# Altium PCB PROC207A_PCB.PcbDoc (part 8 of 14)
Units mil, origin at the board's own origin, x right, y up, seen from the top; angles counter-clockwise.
Board outline 4094.49 x 3724.79 mil, 8 copper layers (Top Layer, L2_GND1, L3_SIG1, L4_PWR1, L5_PWR2, L6_SIG2, L7_GND2, Bottom Layer), stack 58.1 mil thick; 584 components, 399 nets, 8440 pads, 5258 vias.
Unrouted connection lines stored in the file: 9.
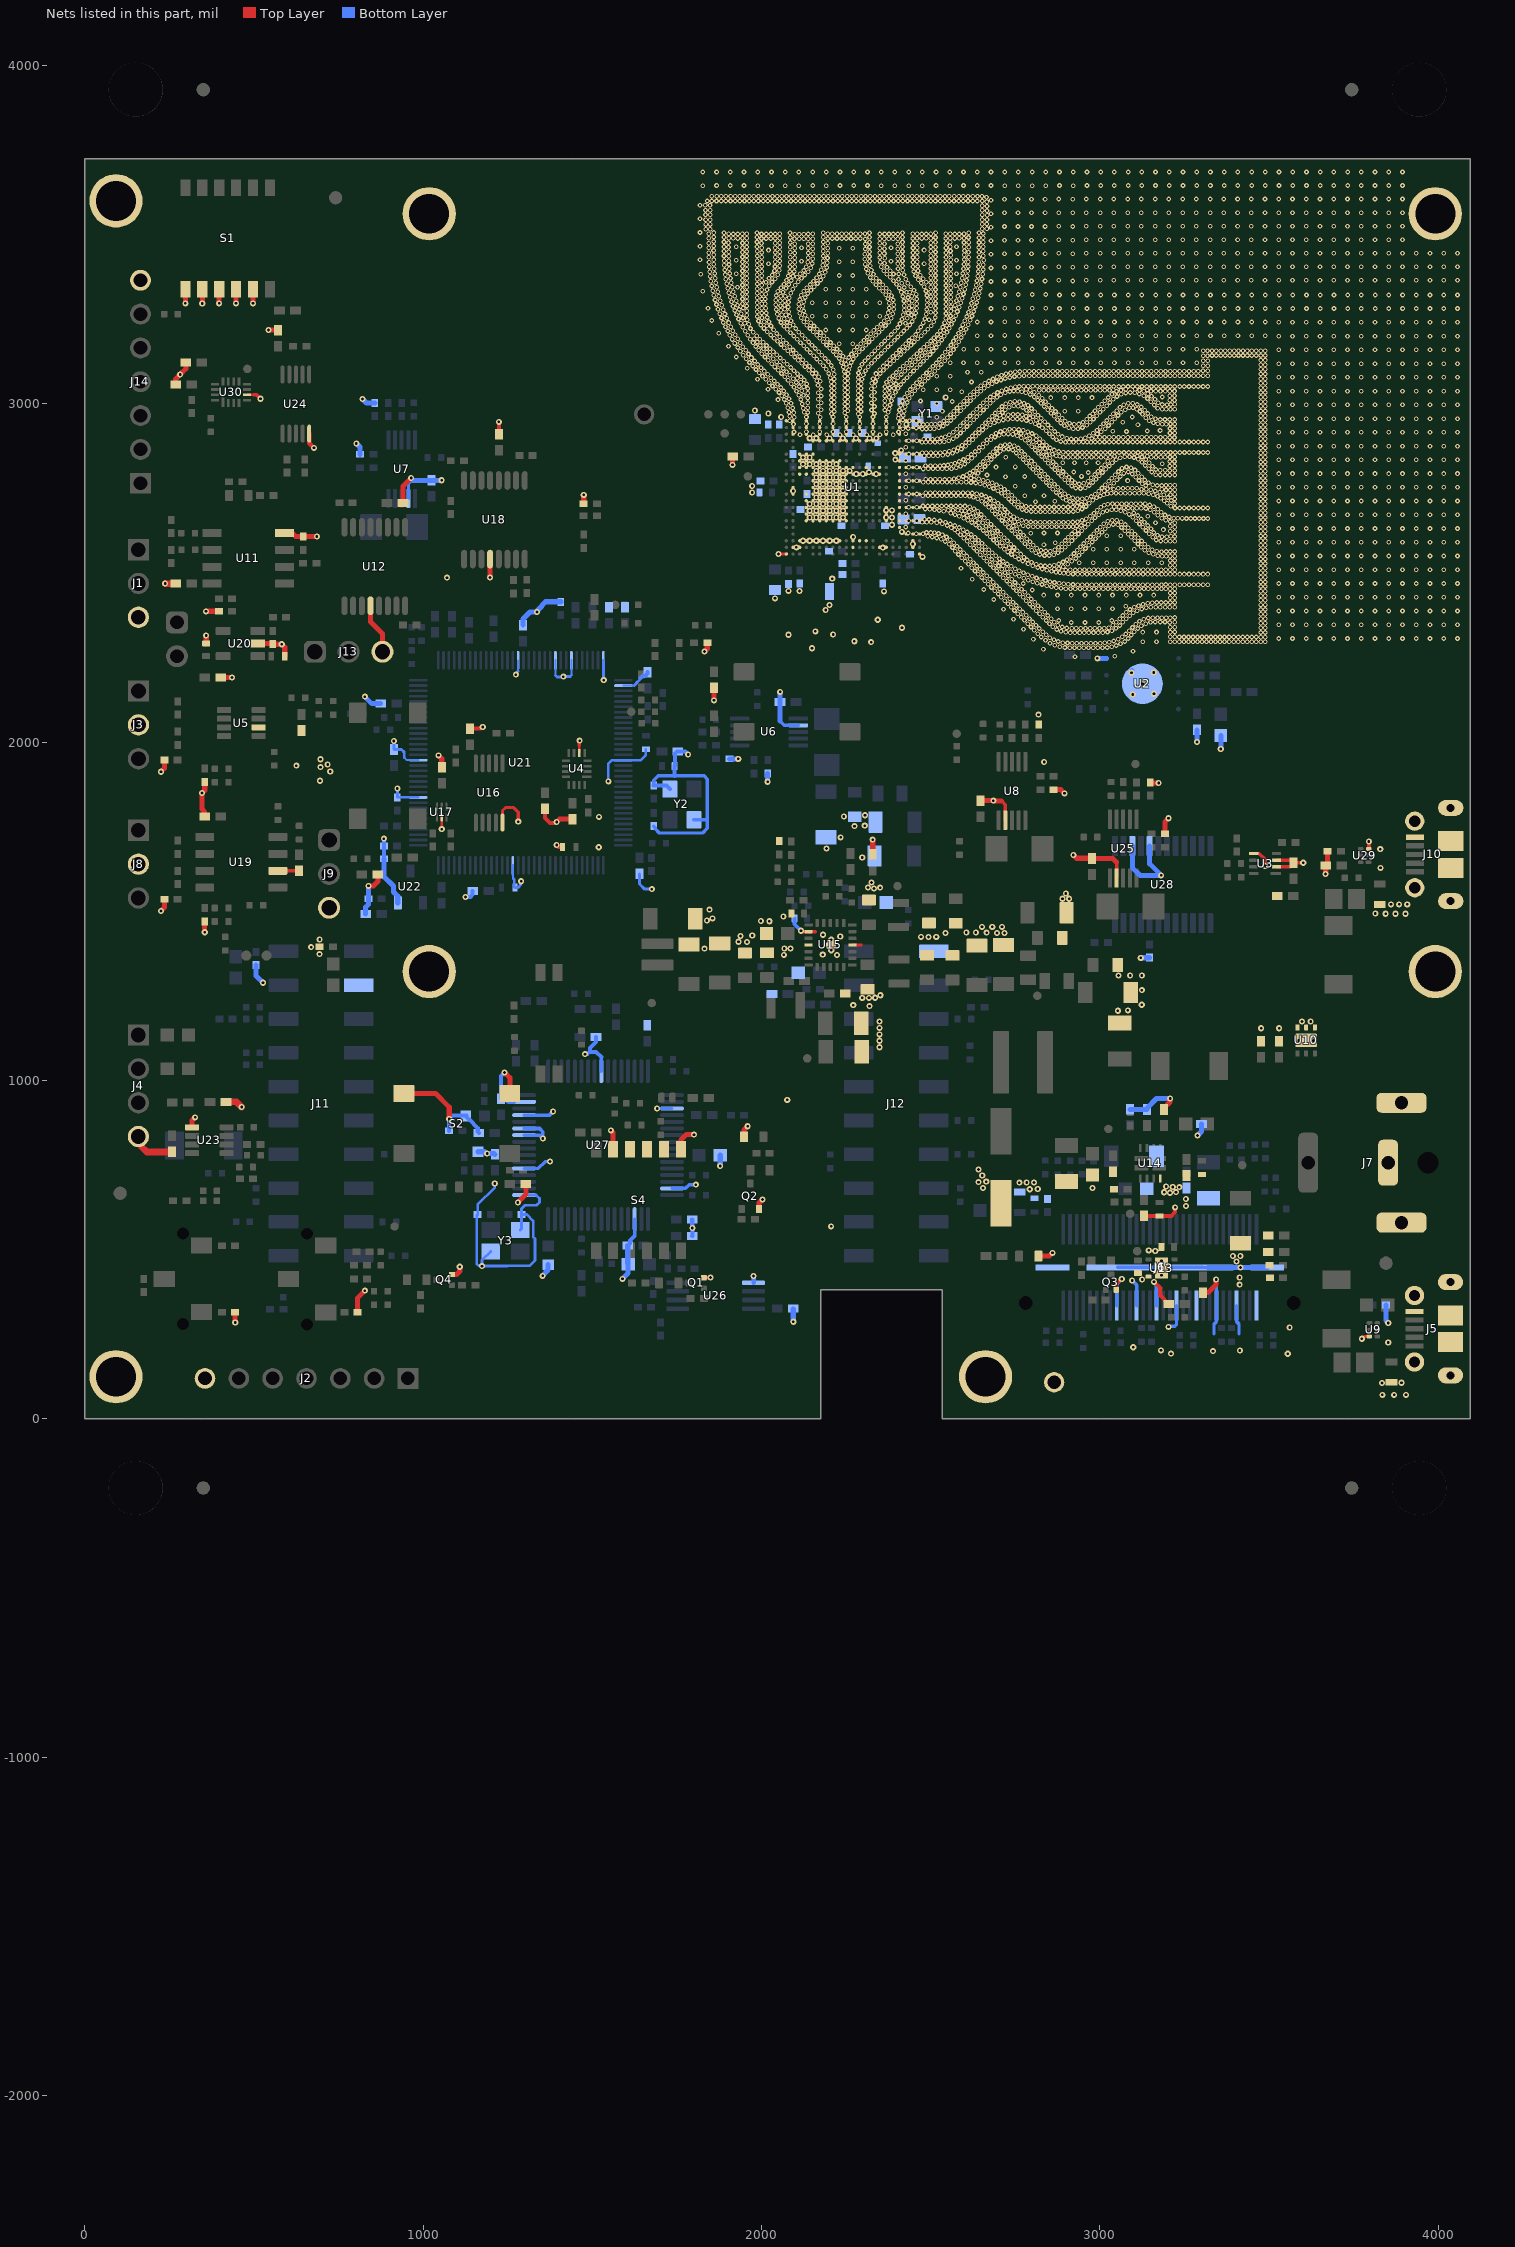
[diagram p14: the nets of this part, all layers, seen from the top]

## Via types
v1: diameter 13.77, hole 7, Top Layer to L2_GND1, tented top, 4306 vias
v2: diameter 18, hole 8, Top Layer to Bottom Layer, tented both sides, 946 vias
v3: diameter 19.68, hole 8, Top Layer to Bottom Layer, tented both sides, 6 vias

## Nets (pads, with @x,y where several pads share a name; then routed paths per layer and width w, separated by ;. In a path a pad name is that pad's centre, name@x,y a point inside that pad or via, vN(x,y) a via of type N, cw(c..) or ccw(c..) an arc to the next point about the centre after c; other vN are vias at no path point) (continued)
GND: C1.1 C2.1 C3.1 C4.1 C5.1 C6.2 C7.1 C8.1 C9.1 C10.1 C11.1 C12.1 C13.2 C14.1 C15.2 C16.1 C17.1 C18.1 C19.1 C20.1 C21.1 C22.1 C24.1 C25.1 C26.1 C27.1 C30.2 C31.2 C32.1 C33.1 C34.2 C35.1 C36.2 C37.1 C38.1 C39.1 C40.2 C41.2 C42.1 C43.2 C44.2 C45.1 C46.1 C47.2 C48.2 C49.2 C50.2 C51.2 C52.1 C53.2 C54.2 C55.2 C56.2 C57.2 C58.2 C59.2 C60.2 C61.2 C62.2 C63.2 C64.2 C65.2 C66.2 C67.1 C68.2 C70.2 C71.2 C72.1 C73.2 C74.2 C75.1 C76.2 C77.1 C78.1 C79.2 C80.2 C81.2 C82.1 C83.2 C84.2 C85.1 C86.1 C87.2 C88.1 C89.2 C90.2 C91.1 C92.2 C93.2 C94.2 C95.1 C96.1 C97.1 C98.1 C99.1 C100.2 C102.1 C103.1 C104.2 C105.2 C106.1 C107.2 C108.2 C109.1 C110.1 C111.1 C112.1 C113.1 C114.2 C115.2 C116.1 C117.1 C118.1 C119.2 C120.2 C121.1 C123.2 C124.2 C125.1 C126.1 C127.2 C128.2 C130.2 C131.1 C132.2 C133.2 C134.1 C135.2 C136.2 C137.2 C138.2 C139.2 C140.2 C141.2 C142.1 C143.2 C144.2 C145.2 C146.1 C147.2 C148.2 C149.1 C150.2 C151.1 C152.2 C153.2 C154.1 C155.1 C156.1 C157.1 C158.2 D6.1 D10.1 J1.3 J2.7 J3.2 J4.4 J5.5 J5.6 J5.7 J5.8 J5.9 J5.10 J5.11 J6.18 J6.24 J6.30 J6.36 J6.42 J6.48 J6.54 J6.60 J6.MP1 J6.MP2 J6.MP3 J6.MP4 J7.2 J7.S1 J7.S2 J8.2 J9.3 J10.5 J10.6 J10.7 J10.8 J10.9 J10.10 J10.11 J11.4 J12.2 J13.3 J14.7 pad.TH1 pad.TH2 pad.TH9 pad.TH10 Q1.2 Q2.2 Q3.2 Q4.2 R6.1 R10.2 R11.1 R20.1 R23.1 R33.1 R57.1 R71.1 R72.1 R73.2 R74.1 R75.1 R84.1 R86.1 R92.1 R101.1 R103.1 R113.1 R114.1 R116.1 R117.1 R144.1 R148.1 R150.1 R158.1 R162.1 R191.2 R194.2 R205.1 R208.1 R215.2 R218.1 R234.1 R239.1 R260.1 R265.2 R272.1 R276.2 R289.1 S1.7 S1.8 S1.9 S1.10 S1.11 S2.1 S2.2 S4.7 S4.8 S4.9 S4.10 S4.11 TP21.1 U1.A1 U1.A2 U1.A4 U1.A6 U1.A8 U1.A10 U1.A12 U1.A14 U1.A16 U1.A18 U1.A21 U1.AA1 U1.AA21 U1.B1 U1.B2 U1.B4 U1.B6 U1.B8 U1.B10 U1.B12 U1.B14 U1.B16 U1.B18 U1.B19 U1.B20 U1.C1 U1.C2 U1.C3 U1.C4 U1.C5 U1.C6 U1.C7 U1.C8 U1.C9 U1.C10 U1.C11 U1.C12 U1.C13 U1.C14 U1.C15 U1.C16 U1.C17 U1.C18 U1.D1 U1.D2 U1.D3 U1.D6 U1.D7 U1.D8 U1.D9 U1.D10 U1.D11 U1.D12 U1.D13 U1.D14 U1.D15 U1.D16 U1.D17 U1.E3 U1.F1 U1.F2 U1.F3 U1.F14 U1.F15 U1.F16 U1.F20 U1.G3 U1.G8 U1.G9 U1.G20 U1.H1 U1.H2 U1.H3 U1.H4 U1.H9 U1.J3 U1.J4 U1.J8 U1.J9 U1.J19 U1.K1 U1.K2 U1.K3 U1.K4 U1.K9 U1.K19 U1.L3 U1.L4 U1.L8 U1.L9 U1.L19 U1.L20 U1.M1 U1.M2 U1.M3 U1.M4 U1.M8 U1.M9 U1.M10 U1.M11 U1.M12 U1.M13 U1.M14 U1.M15 U1.M16 U1.N3 U1.N4 U1.N7 U1.N8 U1.N9 U1.N10 U1.N11 U1.N12 U1.N13 U1.N14 U1.N15 U1.N16 U1.N19 U1.P1 U1.P2 U1.P3 U1.P4 U1.P7 U1.P8 U1.P9 U1.P10 U1.P11 U1.P12 U1.P13 U1.P14 U1.P15 U1.P16 U1.P19 U1.R3 U1.R4 U1.R7 U1.R8 U1.R9 U1.R10 U1.R11 U1.R12 U1.R13 U1.R14 U1.R15 U1.R16 U1.R19 U1.T1 U1.T2 U1.T3 U1.T4 U1.T7 U1.T8 U1.T9 U1.T10 U1.T11 U1.T12 U1.T13 U1.T14 U1.T15 U1.T16 U1.T19 U1.U3 U1.U4 U1.U6 U1.U7 U1.U8 U1.U9 U1.U10 U1.U11 U1.U12 U1.U13 U1.U14 U1.U15 U1.U16 U1.U19 U1.V1 U1.V2 U1.V3 U1.V6 U1.V7 U1.V8 U1.V9 U1.V12 U1.V13 U1.V14 U1.V15 U1.V16 U1.V19 U1.W3 U1.W6 U1.W7 U1.W8 U1.W9 U1.W19 U1.W20 U1.Y1 U1.Y2 U1.Y3 U1.Y11 U1.Y12 U1.Y20 U2.4 U2.9 U3.2 U3.3 U3.5 U4.6 U5.2 U6.7 U7.7 U8.7 U9.3 U10.1 U10.2 U10.3 U10.7@3610.07,1118.68 U11.4 U12.4 U13.3 U13.7@3182.65,445.74 U14.12 U15. U15.2 U15.4 U15.16 U16.5 U17.2 U18.4 U19.2 U20.2 U21.10 U21.17 U21.48 U21.55 U21.58 U21.64 U21.66 U21.80 U21.114 U22.2 U23.5 U24.5 U25.7 U26.5 U27.1 U27.5 U27.10 U27.11 U27.13 U27.15 U27.25 U27.35 U27.47 U27.51 U28.3 U28.5 U29.3 U30.6 Y1.2 Y1.4 Y2.2 Y2.4 Y3.2 Y3.4 | length 10594.6
  Top Layer w6.5: v2(1054.79,1743.16) U17.2@1054.8,1778.05
  Top Layer w7: U30.6@479.11,3026.97 498.53,3026.97 ; U4.6@1461.61,1968.51 1461.61,1991.8
  Top Layer w9: U16.5@1234.33,1762.65 1234.33,1798.01 1243.1,1806.78 1267.22,1806.78 1280.94,1793.06 v2(1280.94,1765.37)
  Top Layer w10: Q1.2@1829.27,417.33 1849.22,417.33 v2(1849.44,417.55) ; v2(2050.39,2556.74) 2050.56,2556.57 2073.3,2556.57 U1.AA21@2073.47,2556.4 ; U1.Y20@2093.15,2576.08 v2(2103,2576.08) U1.W20@2112.84,2576.08 ; U15.2@2138.7,1440.14 2159.3,1440.14 2159.35,1440.09 ; U15.16@2268.62,1400.77 2295.72,1400.77 ; U1.G20@2349.06,2576.08 U1.F20@2368.75,2576.08 ; U1.B20@2447.49,2576.08 v2(2447.49,2585.92) U1.B19@2447.49,2595.77 ; U1.A21@2467.17,2556.4 2467.43,2556.4 2475.67,2548.16 v2(2475.93,2548.16) ; 2709.76,1826.64 2720.79,1815.61 U8.7@2720.79,1769.27 ; C133.2@2976.64,1657.11 C133.2@2977.36,1656.39 ; Q3.2@3048.73,381.35 3048.73,397.24 v2(3064.99,413.5) ; U25.7@3049.64,1599.03 3049.64,1645.37 ; U3.5@3464.21,1671.03 3471.71,1671.03 3489,1653.74 v2(3489,1634) ; U3.2@3522.36,1631.66 3563.97,1631.66 3572.12,1639.81 C36.2@3572.12,1643.75 ; U3.3@3522.36,1651.35 3564.52,1651.35 C36.2@3572.12,1643.75 ; v2(3601.47,1643.75) C36.2@3572.12,1643.75 ; v2(3774.61,236.71) 3776.77,236.71 3783.6,243.53 U9.3@3796.72,243.53
  Top Layer w10.8: 498.53,3026.97 507.35,3026.97 v2(518.82,3015.49) ; U19.2@570.55,1620.14 632.82,1620.14 C110.1@632.96,1620 ; 1461.61,1991.8 1461.61,2004.04 v2(1462.35,2004.78) ; v2(2116.54,1442.8) 2117.92,1441.42 2123.04,1441.42 2124.33,1440.14 U15.2@2132.29,1440.14
  Top Layer w12: U24.5@663.06,2912.26 663.06,2883.9 v2@676.55,2870.41 ; C104.2@1138.39,2040.95 1169.79,2040.95 1174.26,2045.42 v2(1175.88,2045.42) ; C107.2@1223.43,2910.43 1223.43,2947.21 v2(1223.53,2947.31) ; R6.1@1360.12,1803.04 1360.12,1775.81 1374.18,1761.75 1390.61,1761.75 1392.95,1764.09 v2(1394.57,1764.09) ; v2(1394.47,1696.19) 1399.74,1690.92 C108.2@1411.68,1690.92 ; R33.1@3130.93,600.03 C68.2@3175.93,600.03 3211.37,600.03 3222.8,611.46 v2(3222.8,625.19) ; v2(3160.39,404.95) 3178.79,386.55 3178.79,364.8 R92.1@3203.79,339.8 ; U29.3@3795.04,1684.93 3795.14,1685.03 3795.14,1706.42 v2(3795.24,1706.52)
  Top Layer w15: v2@224.29,1501.17 234.64,1511.53 C111.1@234.64,1535.77 ; v2@224.45,1912.88 234.81,1923.24 C39.1@234.81,1947.48 ; C136.2@267.48,3058.04 267.48,3073.34 v2(281.32,3087.18) 298.33,3104.19 R272.1@298.33,3122.76 ; v2@296.89,3298.8 S1.7@296.89,3339.18 ; U23.5@316.77,861.92 316.77,882.42 v2(325.68,891.33) ; v2@345.5,3297.83 346.23,3297.83 347.04,3298.64 S1.8@347.04,3339.03 ; R144.1@354.01,1470.77 v2(354.07,1438.37) v2(354.07,1438.37) ; C109.1@354.01,1780.14 354.01,1794.45 345.82,1802.65 v2(345.82,1849.79) 354.18,1858.16 R71.1@354.18,1882.48 ; v2(357.7,2386.96) 357.98,2387.24 R158.1@395.99,2387.24 ; v2@396.89,3298.8 S1.9@396.89,3339.18 ; C38.1@401.43,2191.85 434.53,2191.85 v2(434.67,2191.71) ; R205.1@443.81,315.23 444.01,315.02 444.01,284.74 v2(444.22,284.54) ; v2@446.89,3298.8 S1.10@446.89,3339.18 ; v2@496.89,3298.8 S1.11@496.89,3339.18 ; U20.2@510.67,2291.81 553.7,2291.81 R86.1@555.67,2289.84 v2(581.89,2289.84) 590.67,2281.05 C51.2@590.67,2254.41 ; v2(542.61,3218.78) 542.87,3218.52 570.41,3218.52 C135.2@570.67,3218.25 ; U11.4@590.18,2618.79 612.27,2618.79 622.9,2608.16 R162.1@645.19,2608.16 685.49,2608.16 v2(685.64,2608.3) ; R208.1@806.26,314.86 806.26,357.81 v2(827.31,378.87) ; v2(838.3,1575.48) 852.9,1575.48 865.89,1588.47 R215.2@865.89,1609.44 ; U12.4@844.1,2403.24 844.1,2356.36 879.43,2321.03 J13.3@879.43,2267.59 ; C41.2@940.24,2707.58 940.24,2757.15 v2(964.38,2781.29) ; S2.1@943.03,961.54 1036.63,961.54 1076.89,921.27 v2(1076.89,886.08) ; v2(1045.06,1961.26) 1054.8,1951.51 C52.1@1054.8,1925.79 ; Q4.2@1084.87,426.48 1098.61,426.48 1108.57,436.44 1107.86,437.15 v2(1107.86,449.58) ; v2(1197.46,2487.03) 1197.57,2487.14 1197.57,2541.45 U18.4@1197.68,2541.56 ; v2(1240.43,1023.85) 1256.02,1008.27 S2.2@1256.02,961.54 ; v2(1279.6,639.72) 1303.26,663.38 C53.2@1303.26,694.37 ; v2(1394.57,1764.09) 1403.26,1772.77 C40.2@1441.72,1772.77 ; C134.1@1474.49,2705 v2(1474.49,2731.49) ; v2(1554.55,852.9) 1561.51,845.93 S4.11@1561.51,796.87 ; S4.7@1761.51,796.87 1761.51,824.37 1778.08,840.94 1798.63,840.94 1798.8,840.77 1799.27,840.77 v2@1799.44,840.94 ; v2(1831.59,2268.33) 1831.59,2268.43 1839.67,2276.51 R276.2@1839.67,2294.33 ; v2(1859.79,2124) R265.2@1859.79,2160.77 ; v2(1914.48,2820.04) 1914.67,2820.23 1914.67,2844.11 C31.2@1915.05,2844.49 ; D10.1@1948.18,834.24 1948.29,834.35 1948.29,854.31 v2(1958.9,864.93) ; Q2.2@1992.56,620.43 1992.56,637.94 v2(2003.21,648.59) ; C59.2@2647.79,1827.36 2648.11,1827.68 2684.91,1827.68 2685.88,1826.72 2688,1826.72 2688.08,1826.64 2709.76,1826.64 ; D6.1@2818.58,481.14 2850.59,481.14 v2(2860.09,490.65) ; R116.1@2863.48,1859.92 2884.9,1859.92 v2(2895.9,1848.92) ; v2(2921.92,1666.58) 2931.39,1657.11 C133.2@2976.64,1657.11 ; C133.2@2977.36,1656.39 3038.61,1656.39 3049.64,1645.37 ; R150.1@3148.69,1881.62 3150.32,1880 v2@3173.68,1880 ; R74.1@3189.26,914.54 3189.26,918.48 3207.5,936.72 3207.5,946.31 v2(3208.07,946.89) ; R148.1@3192.33,1729.68 3192.33,1764.32 v2@3203.12,1775.11 ; R11.1@3305.55,372.91 3319.86,372.91 3343.99,397.04 v2(3343.99,411.59) ; v2(3667.11,1610.37) 3667.87,1611.13 3667.87,1634.49 3673.11,1639.72 R260.1@3673.11,1677.42 R260.1@3670.89,1679.64
  Top Layer w16: C112.1@358.31,2291.81 358.31,2315.18 v2(358.45,2315.32) ; R84.1@2328.26,1670.63 2328.5,1670.88 v2(2328.5,1712.23)
  Top Layer w20: J4.4@158.07,834.5 166.29,826.28 166.29,805.83 183.05,789.08 C132.2@256.77,789.08 ; v2(237.25,2469.04) 237.5,2468.79 C65.2@268.37,2468.79 ; C123.2@417.15,937.13 448.3,937.13 v2(463.4,922.04)
  Bottom Layer w6: 943.92,1955.22 951.89,1947.26 U21.17@985.36,1947.26 ; 1280.53,2210.56 U21.48@1280.53,2242.37 ; 1390.87,2197.77 U21.55@1390.87,2242.47 ; 1438.11,2198.9 U21.58@1438.11,2242.47 ; U21.66@1591.66,2167.67 1623.73,2167.67
  Bottom Layer w7: C115.2@923.91,1836.96 U21.10@985.36,1836.96 ; U21.114@1264.89,1636.17 1264.95,1612.25 1265.05,1612.14 1265.05,1608.47 1265.2,1608.33 1265.2,1598.11 1266.05,1597.26
  Bottom Layer w8: Y3.2@1199.96,495.1 1173.98,469.11 v2(1173.98,451.33) ; v2(1211.55,695.75) 1211.55,683.98 1160.84,633.28 C147.2@1160.84,604 1158.05,601.2 1158.05,458.47 1163.27,453.25 1172.06,453.25 v2(1173.98,451.33) ; Y3.4@1286.58,558.09 1290.73,562.24 C148.2@1290.73,604 ; U27.1@1298.34,661.42 1333.88,661.42 1343.6,651.7 1343.6,639.9 1335.16,631.46 1301.13,631.46 1290.73,621.05 C148.2@1290.73,604 ; v2(1547.1,1884.39) 1547.29,1884.58 1547.29,1936.92 1557.57,1947.19 U21.80@1591.66,1947.19 1643.19,1947.19 1658,1962 C114.2@1658,1979.25 ; J6.MP3@3302.69,447.65 3319.34,447.65 J6.MP3@3319.56,447.42 ; v2(1173.98,451.33) 1174.42,451.78 1248.33,451.78 1248.77,452.23 1314.64,452.23 1330.71,468.3 1330.71,532.51 1325.13,538.08 1325.13,585.17 1306.3,604 C148.2@1290.73,604
  Bottom Layer w8.7: v2(913.18,2003.61) 913.13,2003.55 C116.1@913.07,1978.49 C116.1@913.07,1978.49 936.06,1978.49 943.92,1970.63 943.92,1955.22 ; C115.2@923.42,1837.44 923.49,1837.51 923.49,1863.23 v2(923.55,1863.29) ; 1266.05,1597.26 1269.09,1594.22 1269.09,1572.03 C127.2@1270.8,1570.32 ; C127.2@1271.13,1570.65 1280.8,1570.65 1287.87,1577.71 1287.87,1587.55 v2(1289.54,1589.21) ; v2(1273.89,2199.95) 1273.89,2202.46 1280.53,2209.1 1280.53,2210.56 ; 1390.87,2197.77 1395.57,2193.07 1413.3,2193.07 v2(1414.23,2194) ; v2@1414.23,2193.4 1414.83,2194 1433.22,2194 1438.11,2198.9 ; U21.64@1532.6,2242.47 1532.6,2184.6 v2(1533.54,2183.66) ; 1623.73,2167.67 1629.88,2173.82 1629.88,2174.98 1642.03,2187.14 1642.03,2189.6 ; C94.2@1639.64,1611.03 1639.64,1581.36 1655.17,1565.83 v2(1675.83,1565.83) ; v2(1691.43,917.1) 1691.54,917.21 1735.24,917.21 U27.35@1735.35,917.33
  Bottom Layer w10: U7.7@955.74,2720.53 956.52,2721.31 956.52,2767.65 957.8,2768.93 ; U27.5@1298.34,740.16 1340.28,740.16 1360.73,760.61 v2(1374.79,760.61) ; U27.13@1298.34,897.64 1373.51,897.64 ; U27.25@1526.69,1027.56 1526.69,1068.99 ; 1625.12,541.01 U27.51@1625.12,590.55 ; C97.1@1681.09,1751.94 1685.93,1747.1 1685.93,1743.78 1697.94,1731.77 1825.65,1731.77 1839.95,1746.06 1839.95,1771.08 ; C98.1@1681.09,1872.51 1681.09,1887.27 1694.28,1900.46 1743.07,1900.46 1830.42,1900.46 1839.95,1890.93 1839.95,1771.08 ; U27.47@1735.35,681.1 1775.28,681.1 1786.07,691.89 1805.57,691.89 v2(1805.9,692.22) ; Y2.2@1800.24,1771.08 1839.95,1771.08 ; 2054.82,2062.65 2067.27,2050.2 U6.7@2108.66,2050.2 ; J6.18@3049.73,334.85 3049.73,398.24 v2(3064.99,413.5) ; J6.MP2@3052.69,447.65 J6.MP3@3302.69,447.65 ; v2(3095.55,408.91) 3108.79,395.67 J6.24@3108.79,334.85 ; v2(3203.26,272.01) 3204.79,273.55 3221.04,273.55 3226.9,279.4 J6.36@3226.9,334.85 ; 3337.63,251.7 3337.63,280.28 3345.01,287.67 J6.48@3345.01,334.85 3345.01,410.56 v2(3343.99,411.59) ; J6.54@3404.07,335.1 3404.07,287.7 3411.45,280.32 3411.45,251.94
  Bottom Layer w10.8: C79.2@2097.33,1479.72 2097.33,1462.01 v2(2116.54,1442.8)
  Bottom Layer w11: U27.10@1298.34,838.58 1343.53,838.58 v2(1353.53,828.58) 1353.53,848.63 1343.88,858.27 U27.11@1298.34,858.27
  Bottom Layer w12: R239.1@883.49,1655.53 C118.1@883.49,1693.47 ; C118.1@883.52,1693.5 883.52,1714.95 v2(883.61,1715.04) ; R218.1@1076.69,851.44 1076.69,885.87 v2(1076.89,886.08) 1087.1,896.29 C145.2@1127.43,896.29 ; v2(1124.87,1542.6) 1139.11,1542.6 1146.14,1549.63 C126.1@1146.14,1560.6 ; C145.2@1126.01,895.34 1126.01,894.35 1135.76,884.6 1136.75,884.6 1161.15,860.2 1161.15,848.74 C146.1@1165.06,844.84 ; v2(1240.43,1023.85) 1230.55,1013.97 C140.2@1230.55,946.37 1241.95,946.37 1251.31,937.01 U27.15@1268.91,937.01 ; 1373.51,897.64 v2@1383.96,908.09 ; v2(1478.22,1078.11) 1479.37,1079.26 1485.83,1079.26 1492.61,1086.04 1492.75,1086.04 ; C153.2@1510.53,1128.96 1510.53,1113.76 1492.75,1095.99 1492.75,1086.04 ; 1526.69,1068.99 1526.54,1068.99 1510.64,1084.89 1491.61,1084.89 1492.75,1086.04 ; C150.2@1604.54,512.55 1605.16,512.55 1610.97,518.36 1610.97,526.86 1625.09,540.98 ; 1642.03,2189.6 1642.71,2189.6 1650.5,2197.39 1657.75,2197.39 1663.56,2203.2 C95.1@1663.56,2207.14 ; C98.1@1681.09,1872.51 1718.5,1872.51 Y2.4@1729.37,1861.63 ; 1743.07,1900.46 1743.07,1929.03 C124.2@1743.32,1929.29 ; C124.2@1743.98,1929.95 1743.98,1966.6 1749.79,1972.41 C125.1@1752.87,1972.41 1774.52,1972.41 v2(1783.2,1963.72) ; C143.2@1795.18,589.26 1795.18,564.81 v2(1795.67,564.32) 1795.67,541.17 C144.2@1795.34,540.83 ; v2(3160.39,404.95) 3160.39,403.61 3167.85,396.15 J6.30@3167.85,334.85
  Bottom Layer w13: U26.5@1976.38,402.27 1976.48,402.37 v2(1976.48,422.24)
  Bottom Layer w15: C119.2@505.82,1341.13 505.82,1337.15 505.5,1336.82 505.5,1309.86 v2(526.29,1289.07) ; v2(802.28,2883.47) 813.05,2872.7 R113.1@813.06,2851.18 ; v2(820.62,3014.87) 832.36,3003.13 R114.1@856.69,3003.13 ; v2(827.43,2134.84) 848.09,2114.19 C106.1@874.28,2114.19 ; C99.1@829.75,1492.45 829.75,1512.5 837.62,1520.38 C102.1@837.62,1537.45 837.96,1537.79 837.96,1575.13 v2(838.3,1575.48) ; R239.1@883.49,1655.53 883.49,1603.31 911.89,1574.91 911.89,1557.59 924.77,1544.71 U22.2@924.77,1525.29 ; 957.8,2768.93 957.8,2773.9 964.38,2780.48 v2(964.38,2781.29) ; v2@963.24,2774.37 964.38,2774.37 1024.89,2774.37 C58.2@1025.06,2774.2 1025.21,2774.35 1054.35,2774.35 v2(1054.5,2774.5) ; C141.2@1161.74,789.55 1181.67,789.55 1186.9,784.32 v2(1189.06,784.32) 1209.09,784.32 C142.1@1211.74,781.67 ; C113.1@1294.66,2346.16 1294.66,2364.4 1315.52,2385.26 v2(1336.22,2385.26) ; v2@1335.19,2386.68 1351.1,2402.59 1351.1,2404.71 1361.7,2415.32 R234.1@1406.98,2415.32 ; v2(1353.14,422.84) 1353.72,423.41 1353.72,424.67 1369.13,440.09 C139.2@1369.13,455.62 ; v2(1588.91,413.93) 1605.89,430.91 C149.1@1605.89,457.21 1604.54,458.57 C150.2@1604.54,512.55 ; v2(1877.76,747.27) 1878.05,747.56 1878.05,779.24 C151.1@1878.34,779.53 ; R103.1@1904.8,1951.15 1931.01,1951.15 v2(1931.3,1950.87) ; R101.1@2018.01,1907.51 2018.09,1907.43 2018.09,1883.32 v2(2018.18,1883.23) ; 2054.82,2062.65 C57.2@2054.82,2119.35 2054.99,2119.52 2054.99,2148.79 v2(2055.16,2148.96) ; v2@2093.85,287.12 C138.2@2093.85,325.27 ; v2(2992.72,2248) U2.4@3019.7,2248 ; R23.1@3089.8,914.94 3138.92,914.94 R20.1@3139.44,914.42 3139.44,918.36 3167.96,946.89 v2(3208.07,946.89) ; v2(3093.55,2205.45) 3095.63,2207.53 U2.9@3095.63,2211.53 ; U28.3@3096.23,1693.39 3096.23,1629.27 3118.82,1606.67 v2(3181.37,1606.67) 3147.41,1640.63 U28.5@3147.41,1693.39 ; v2(3120.98,1362.6) 3121.3,1362.92 3146.51,1362.92 R10.2@3146.83,1363.24 ; v2(3287.5,2000.68) 3287.91,2001.09 C34.2@3287.91,2036.79 ; v2(3288.79,837.59) 3300.8,849.59 R75.1@3300.8,871.32 ; J6.MP3@3319.56,447.42 3415.93,447.42 v2(3416.16,447.19) ; v2(3357.67,1980.33) 3357.91,1980.57 C35.1@3357.91,2019.91 ; v2@3416.16,447.65 J6.MP4@3495.21,447.65 ; R72.1@3846.01,336.63 3846.01,290.76 3852.82,283.96 v2(3852.82,283.15)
